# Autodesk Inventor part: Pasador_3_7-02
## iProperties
Company: COMGRAP
Created: 2008-01
Part Number: Pasador_3_7-02
Document SubType Name: Modeling
Designer: eruiz-tagle
Density: 1.06 g/cm^3
Mass: 0.76612 g
Surface Area: 8.92429 cm^2
Volume: 0.722755 cm^3
Material: ABS Plastic
Author: Esteban
Title: CURSO INVENTOR
Comments: Esta pieza fue creada en el curso de inventor
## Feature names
1. Extrusion1
2. Fillet1
3. Revolution1
4. Mirror1
